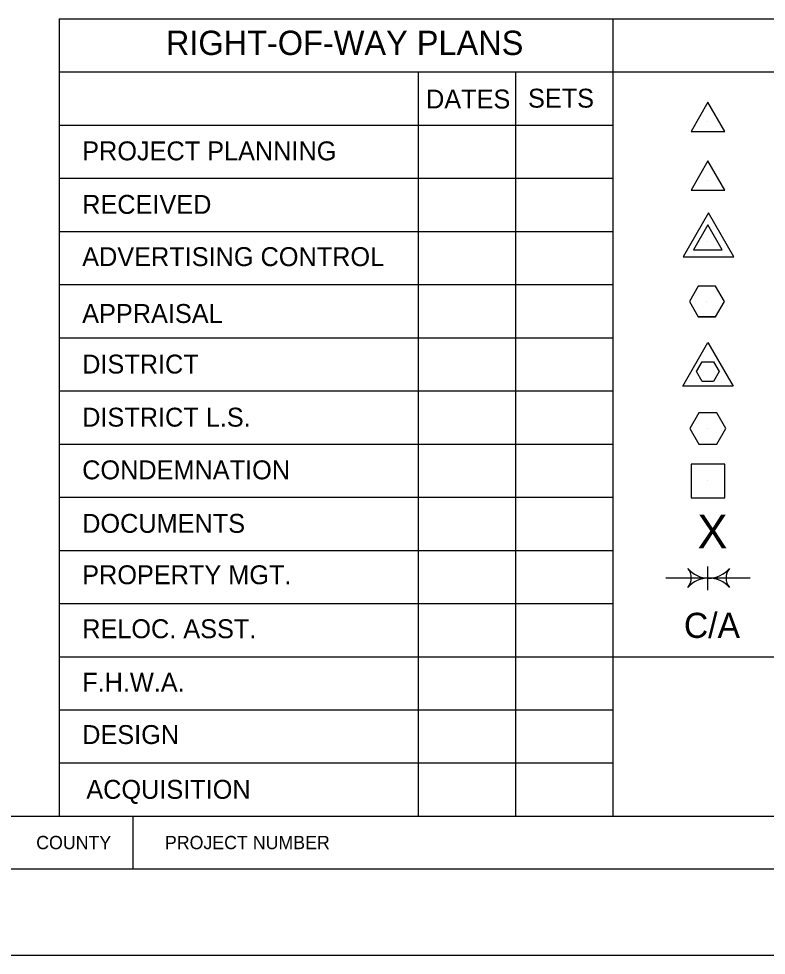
# Model space of a CAD drawing. Extents: x -507127 to -501139, y -509578 to -506434.
# Drawn here: x -505412 to -504858, y -508267 to -507574 of the extents above; entities that cross this region are included whole.
import ezdxf

# ---------------------------------------------------------------- set-up
doc = ezdxf.new("R2010")
doc.units = 0
for name, color, linetype in [('Default', 7, 'Continuous'), ('rowdsnConstructCell', 7, 'Continuous'), ('rowdsnSymbolsProposed', 7, 'Continuous')]:
    doc.layers.add(name, color=color, linetype=linetype)

# ---------------------------------------------------------------- blocks, each defined once
blk = doc.blocks.new('PE intersecting Existing ROW')
at = {"layer": 'Default'}
for p, q in [((-7.75, -4.47), (0, 8.95)), ((0, 8.95), (7.75, -4.47)), ((-3.5, 0), (-1.75, 3.03)), ((-1.75, 3.03), (1.75, 3.03)), ((1.75, 3.03), (3.5, 0)), ((-1.75, -3.03), (-3.5, 0)), ((3.5, 0), (1.75, -3.03)), ((7.75, -4.47), (-7.75, -4.47)), ((1.75, -3.03), (-1.75, -3.03))]:
    blk.add_line(p, q, dxfattribs=at)

msp = doc.modelspace()

# ---------------------------------------------------------------- linework, layer by layer
at = {"layer": 'rowdsnConstructCell'}
for p, q in [((-505381.93, -507573.53), (-504397.68, -507573.53)), ((-505381.93, -507573.53), (-505381.93, -508164.08)), ((-504971.83, -507573.53), (-504971.83, -508164.08)), ((-505381.93, -507612.9), (-504397.68, -507612.9)), ((-505116.18, -507612.9), (-505116.18, -508164.08)), ((-505044.01, -507612.9), (-505044.01, -508164.08)), ((-504901.51, -507649.86), (-504901.51, -507649.86)), ((-505381.93, -507652.27), (-504971.83, -507652.27)), ((-505381.93, -507691.64), (-504971.83, -507691.64)), ((-504901.51, -507693.23), (-504901.51, -507693.23)), ((-505381.93, -507731.01), (-504971.83, -507731.01)), ((-504901.51, -507738.43), (-504901.51, -507738.43)), ((-505381.93, -507770.38), (-504971.83, -507770.38)), ((-504902.28, -507782.97), (-504902.28, -507782.97)), ((-504895.78, -507794.23), (-504908.78, -507794.23)), ((-505381.93, -507809.75), (-504971.83, -507809.75)), ((-505381.93, -507849.12), (-504971.83, -507849.12)), ((-504901.51, -507876.94), (-504901.51, -507876.94)), ((-505381.93, -507888.49), (-504971.83, -507888.49)), ((-504901.51, -507915.83), (-504901.51, -507915.83)), ((-505381.93, -507927.86), (-504971.83, -507927.86)), ((-505381.93, -507967.23), (-504971.83, -507967.23)), ((-504901.51, -507987.87), (-504901.51, -507979.1)), ((-504870.26, -507987.87), (-504932.76, -507987.87)), ((-504901.51, -507996.64), (-504901.51, -507987.87)), ((-504901.51, -507987.87), (-504901.51, -507987.87)), ((-504901.32, -507987.8), (-504901.32, -507987.8)), ((-505381.93, -508006.6), (-504971.83, -508006.6)), ((-505381.93, -508045.97), (-504971.83, -508045.97)), ((-504971.83, -508045.97), (-504397.68, -508045.97)), ((-505381.93, -508085.34), (-504971.83, -508085.34)), ((-505381.93, -508124.71), (-504971.83, -508124.71)), ((-507022.35, -508164.08), (-504397.68, -508164.08)), ((-505381.93, -508164.08), (-504397.68, -508164.08)), ((-505327.09, -508203.45), (-505327.09, -508164.08)), ((-505327.09, -508203.45), (-505327.09, -508170.32)), ((-504397.68, -508203.45), (-507022.35, -508203.45)), ((-507126.68, -508267.1), (-504293.35, -508267.1))]:
    msp.add_line(p, q, dxfattribs=at)
for points in [[(-504914.01, -507657.07), (-504889.01, -507657.07), (-504901.51, -507635.42)], [(-504914.01, -507700.45), (-504889.01, -507700.45), (-504901.51, -507678.79)], [(-504919.82, -507749.84), (-504882.32, -507749.84), (-504901.07, -507717.37)], [(-504912.13, -507744.56), (-504890.88, -507744.56), (-504901.51, -507726.16)], [(-504908.78, -507794.23), (-504895.78, -507794.23), (-504889.28, -507782.97), (-504895.78, -507771.71), (-504908.78, -507771.71), (-504915.28, -507782.97)], [(-504914.01, -507928.33), (-504889.01, -507928.33), (-504889.01, -507903.33), (-504914.01, -507903.33)]]:
    msp.add_lwpolyline(points, close=True, dxfattribs=at)
msp.add_lwpolyline([(-504908.17, -507888.49), (-504894.84, -507888.49), (-504888.17, -507876.94), (-504894.84, -507865.4), (-504908.17, -507865.4), (-504914.84, -507876.94), (-504908.17, -507888.49)], dxfattribs=at)
for centre, radius, start, end in [((-504924.44, -507987.6), 10.63, 318.46008, 40.93465), ((-504901, -507967.72), 20.11, 219.9762, 319.74739), ((-504877.13, -507987.62), 10.97, 140.97973, 220.82969), ((-504900.99, -508008.47), 20.71, 41.30244, 138.42453)]:
    msp.add_arc(centre, radius, start, end, dxfattribs=at)

# ---------------------------------------------------------------- block references
at = {"layer": 'rowdsnSymbolsProposed', "xscale": 2.4, "yscale": 2.4}
msp.add_blockref('PE intersecting Existing ROW', (-504901.51, -507834.82), dxfattribs=at)

# ---------------------------------------------------------------- texts
at = {"layer": 'rowdsnConstructCell'}
for s, height, p in [('RIGHT-OF-WAY PLANS', 18, (-505302.97, -507600.39)), ('DATES', 14, (-505110.28, -507640.01)), ('SETS', 14, (-505034.76, -507639.38)), ('PROJECT PLANNING', 14, (-505364.94, -507678.39)), ('RECEIVED', 14, (-505364.94, -507718.02)), ('ADVERTISING CONTROL', 14, (-505364.94, -507756.72)), ('APPRAISAL', 14, (-505364.94, -507798.84)), ('DISTRICT', 14, (-505364.94, -507836.29)), ('DISTRICT L.S.', 14, (-505364.94, -507875.61)), ('CONDEMNATION', 14, (-505364.94, -507914.62)), ('DOCUMENTS', 14, (-505364.94, -507954.25)), ('X', 25, (-504909.28, -507965.85)), ('PROPERTY MGT.', 14, (-505364.94, -507992.32)), ('RELOC. ASST.', 14, (-505364.94, -508032.29)), ('C/A', 18.622, (-504919.28, -508032.08)), ('F.H.W.A.', 14, (-505364.94, -508071.94)), ('DESIGN', 14, (-505364.94, -508110.65)), ('ACQUISITION', 14, (-505361.88, -508151.23)), ('COUNTY', 9.843, (-505399, -508188.53)), ('PROJECT NUMBER', 9.8425, (-505303.66, -508188.53))]:
    msp.add_text(s, height=height, dxfattribs=at).set_placement(p)

doc.saveas('drawing.dxf')
